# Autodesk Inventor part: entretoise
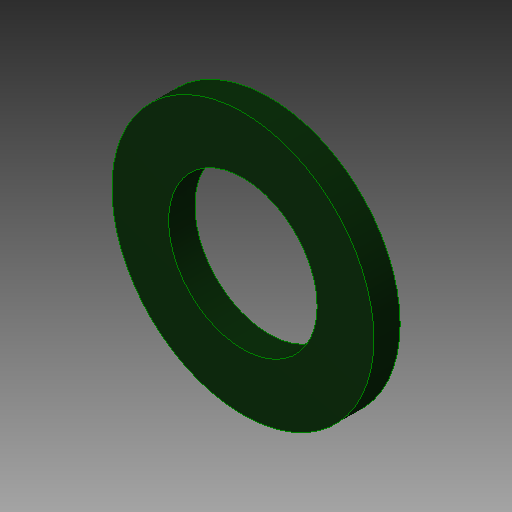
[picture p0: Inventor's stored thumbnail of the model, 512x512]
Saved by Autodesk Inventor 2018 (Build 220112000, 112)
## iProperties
Created: 2009-05
Part Number: entretoise
Material: Générique
Document SubType Name: Modeling
Designer: TJ
Density: 1 g/cm^3
Appearance: Par défaut
Sending System: SolidWorks 2008
Last Author: Roger
Last Saved: 2011-02-17
Author: TJ
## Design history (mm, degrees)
extrude "Extrusion1"
node "Solide1"
